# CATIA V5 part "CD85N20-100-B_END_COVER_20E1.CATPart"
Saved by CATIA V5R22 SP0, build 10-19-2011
Part number: CD85N20-100-B_END_COVER_20E1
Revision: ANY
Definition: UNKNOWN
Nomenclature: CD85N20-100-B_END_COVER_20E1
Source: Unknown
Bounding box of the stored display mesh (mm): x -12 to 12, y -12 to 12, z 0 to 35
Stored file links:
  U:\S9A\PER\CAO\Assemblage\Reservoir_Flacon\Verin\Poussoir_2\CD85N20-100-B_END_COVER_20E1.CATPart
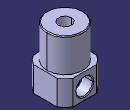
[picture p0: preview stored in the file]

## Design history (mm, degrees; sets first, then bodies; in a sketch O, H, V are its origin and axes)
Body1 "Chamfer1" (main body)
  Solid1: solid without history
